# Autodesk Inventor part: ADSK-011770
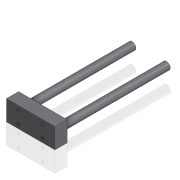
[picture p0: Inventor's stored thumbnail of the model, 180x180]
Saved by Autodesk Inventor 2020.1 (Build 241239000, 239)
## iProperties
Created: 2000-01
Part Number: ADSK-011770
Material: Acier doux
Document SubType Name: Modeling
Designer: sspink
Density: 7.86 g/cm^3
Appearance: Metal-Steel(Polish)
Mass: 652.858 g
Surface Area: 222.956 cm^2
Volume: 83.0608 cm^3
Control State: 0
Checked Out: False
Master: False
Shininess: 0.0
Length Units: 11269
Angle Units: 11279
Time Units: 11290
Mass Units: 11283
Length Display Precision: 3
Angle Display Precision: 2
Compacted: True
Dimensions: 76,2x31,7x186,3 mm
Mass: 0,653 kg
Density: 0.0
Volumn: 0.0
Area: 0.0
PropertySet Name: Model Information
Author: sspink
Revision Number: -
Title: ADSK-011770
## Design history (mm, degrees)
node "Solide1"
  node "Extrusion1" dims "d2" = 19.05, "d3" = 0
  node "Extrusion2" dims "d7" = 167.2336, "d8" = 0
  node "Hole1" dims "d13" = 4.134, "d14" = 9.525, "d15" = 6.35, "d16" = 60 deg, "d17" = 14.2, "d18" = 118 deg, "d19" = 10
sketch "Sketch3"
  geometry: L1 (0, 0)-(-76.2, 0) reference; L2 (0, 31.75)-(0, 0) reference; L3 (-76.2, 31.75)-(0, 31.75) reference; L4 (-76.2, 0)-(-76.2, 31.75) reference; L5 (-76.2, 15.875)-(0, 15.875); L6 (-38.1, 31.75)-(-38.1, 0); 4 further points
  constraints: 4 end point, 4 midpoint, 2 horizontal alignment, 2 vertical alignment
  dimensions: "d9" = 19 distance of point (-57.1, 6.375) point (-57.1, 25.375); "d10" = 9.5 distance from line of L5 point (-57.1, 25.375) (= 0.5 x d9); "d11" = 38 distance of point (-19.1, 25.375) point (-57.1, 25.375); "d12" = 19 distance from line of L6 point (-57.1, 25.375) (= 0.5 x d11)
node "Corps solides"
node "Corps surfaciques"
sketch "Sketch1"
  geometry: L1 (0, 0)-(-76.2, 0) reference; L2 (-76.2, 0)-(-76.2, 31.75); L3 (-76.2, 31.75)-(0, 31.75); L4 (0, 31.75)-(0, 0) reference
  constraints: 8 end point, 2 horizontal, 2 parallel, 1 perpendicular, 1 vertical
  dimensions: "d0" = 76.2 distance of L1.start L1.end; "d1" = 31.75 distance of L3.end L1.start
sketch "Sketch2"
  geometry: L1 (0, 0)-(0, 31.75) reference; L2 (76.2, 0)-(0, 0) reference; L3 (76.2, 31.75)-(76.2, 0) reference; L4 (0, 31.75)-(76.2, 31.75) reference; L5 (0, 15.875)-(76.2, 15.875); L6 (38.1, 31.75)-(38.1, 0); C1 r 5.994 at (11.1, 15.875); C2 r 5.994 at (65.1, 15.875)
  constraints: 4 end point, 4 midpoint, 2 centre point, 2 point on line, 1 equal radius
  dimensions: "d4" = 54.0004 distance of C2.centre C1.centre; "d5" = 27.0002 distance from line of C2.centre L6 (= 0.5 x d4); "d6" = 11.9888 diameter of C1
